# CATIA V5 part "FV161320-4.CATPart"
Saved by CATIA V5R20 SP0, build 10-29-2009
Part number: FV161320-4
Revision: ANY
Definition: UNKNOWN
Nomenclature: FV161320-4
Source: Unknown
Bounding box of the stored display mesh (mm): x -6.24 to 6.24, y 0 to 1.8, z -6.4 to 6.4
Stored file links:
  C:\Users\Utente\Desktop\IO LAVORO\3D X SITO CF\CUMSA\3D files FV\FV 161320\FV161320-4.CATPart
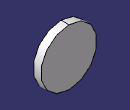
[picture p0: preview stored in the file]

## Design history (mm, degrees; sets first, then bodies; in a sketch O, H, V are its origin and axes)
Body1 "Saliente-Extruir1" (main body)
  Solid1: solid without history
